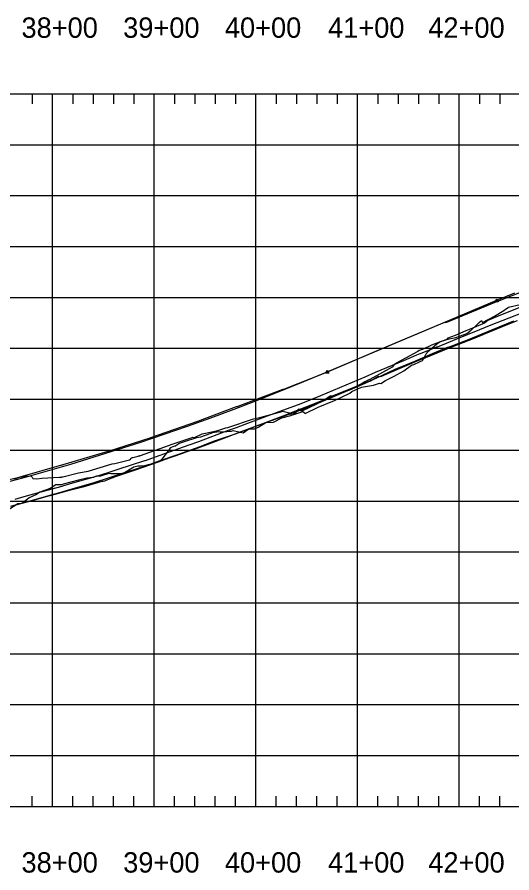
# Model space of a CAD drawing. Extents: x 704797 to 712284, y 374940 to 376945.
# Drawn here: x 710899 to 711386, y 375160 to 376001 of the extents above; entities that cross this region are included whole.
import ezdxf

# ---------------------------------------------------------------- set-up
doc = ezdxf.new("R2010")
doc.units = 0
for name, color, linetype in [('10', 7, 'Continuous'), ('12', 7, 'Continuous'), ('13', 7, 'Continuous'), ('48', 7, 'Continuous'), ('61', 7, 'Continuous'), ('Existing', 7, 'Continuous')]:
    doc.layers.add(name, color=color, linetype=linetype)

msp = doc.modelspace()

# ---------------------------------------------------------------- linework, layer by layer
for points in [[(711370.57, 375724.17), (711372.07, 375721.17), (711369.07, 375721.17)], [(711204.02, 375653.89), (711205.52, 375650.89), (711202.52, 375650.89)]]:
    msp.add_lwpolyline(points, close=True)
at = {"layer": '10'}
for points in [[(711395.06, 375716.31), (711375.98, 375708.74), (711361.85, 375702.63), (711358.48, 375700.14), (711346.85, 375695.38), (711340.37, 375692.49), (711329.63, 375688.11), (711322.41, 375685.32), (711321.97, 375685.1), (711321.79, 375684.52), (711320.57, 375683.8), (711306.63, 375678.69), (711298.15, 375674.56), (711294.47, 375673.39), (711293.09, 375672.2), (711273.16, 375661.51), (711270.08, 375659.77), (711267.84, 375657.05), (711245.72, 375644.93), (711245.03, 375644.56), (711240.88, 375642.64), (711238.18, 375640.76), (711230.95, 375637.39), (711208.95, 375628.43), (711206.97, 375628.56), (711199.57, 375623.37), (711178.93, 375613.85), (711175.62, 375615.8), (711172.19, 375611.49), (711167.8, 375609.04), (711159.11, 375606.84), (711150.82, 375602.53), (711143.47, 375602.31), (711136.65, 375597.9), (711132.16, 375595.88), (711126.95, 375596.06), (711121.23, 375592.01), (711117.08, 375592.94), (711111.6, 375594.34), (711111.29, 375594.52), (711109.64, 375593.9), (711107.61, 375593.74), (711105.2, 375593.38), (711099.61, 375593.01), (711098.5, 375593.15), (711096.78, 375593.39), (711095.4, 375593.2), (711093.67, 375592.98), (711092.95, 375592.86), (711091.06, 375592.5), (711088.52, 375591.59), (711079.46, 375588.28), (711075.5, 375587.41), (711063.24, 375583.73), (711058.25, 375581.95), (711057.93, 375581.61), (711053.96, 375578.95), (711053.87, 375579.22), (711050.62, 375577.86), (711049.18, 375577.17), (711048.59, 375576.04), (711048.25, 375574.83), (711047.31, 375574.3), (711041.5, 375566.77), (711039.83, 375564.79), (711033.82, 375562.86), (711030.69, 375561.69), (711027.75, 375560.96), (711022.98, 375559.57), (711017.83, 375559.7), (711013.9, 375558.74), (711004.55, 375553.02), (711000.7, 375552.08), (710991.25, 375552.12), (710989.65, 375552.61), (710989.29, 375552.5), (710981.01, 375549.86), (710977.86, 375550), (710977.02, 375549.73), (710976.06, 375549.48), (710976.03, 375549.47), (710974.67, 375548.8), (710974.3, 375548.58), (710974.06, 375548.62), (710973.74, 375548.68), (710967.55, 375547.87), (710959.49, 375545.99), (710944.43, 375541.98), (710942.84, 375541.51), (710942.59, 375541.39), (710942.57, 375541.35), (710942.46, 375541.45), (710939.77, 375541.42), (710936.97, 375541.39), (710931.6, 375537.6), (710921.46, 375534.22), (710917.95, 375531.87), (710910.98, 375528.55), (710909.09, 375527.4), (710904.54, 375523.57), (710904.15, 375523.34), (710903.33, 375523.06), (710899.81, 375522.54), (710890.51, 375516.7)], [(710896.37, 375547.23), (710901.24, 375548.79), (710907.58, 375549.96), (710907.95, 375549.99), (710912.5, 375550.31), (710913.73, 375548.73), (710914.51, 375547.66), (710918.45, 375547.33), (710923.29, 375547.83), (710940.85, 375548.87), (710942.19, 375548.86), (710942.84, 375548.99), (710943.47, 375549.06), (710943.96, 375549.11), (710959.48, 375553), (710968.83, 375554.71), (710992.64, 375561.82), (710994.98, 375562.28), (711009.52, 375566.03), (711009.54, 375566.03), (711009.55, 375566.04), (711009.58, 375566.05), (711010.53, 375566.55), (711010.76, 375567.2), (711011.07, 375567.92), (711011.17, 375567.93), (711011.21, 375567.94), (711011.54, 375567.97), (711011.68, 375567.99), (711012.4, 375568.07), (711012.67, 375568.12), (711018.19, 375569.66), (711018.8, 375569.79), (711019.16, 375569.87), (711019.41, 375569.92), (711019.73, 375569.98), (711019.93, 375570.01), (711019.97, 375570.02), (711020.08, 375570.03), (711020.23, 375570.08), (711048.96, 375580.34), (711050.35, 375580.87), (711070.1, 375587.67), (711071.7, 375588.16), (711073.41, 375587.77), (711073.7, 375587.95), (711074.19, 375588.18), (711081.09, 375591.32), (711090.57, 375593.31), (711092.19, 375593.78), (711097.27, 375595.21), (711104.15, 375597.24), (711106.29, 375597.8), (711131.59, 375606.34), (711137.8, 375607.51), (711160.58, 375613.81), (711161.45, 375613.37), (711161.63, 375613.42), (711166.97, 375612.09), (711168.4, 375610.45), (711168.63, 375610.39), (711170.2, 375610.02), (711180, 375613.29), (711182.62, 375611.47), (711182.93, 375611.67), (711194.26, 375617.34), (711195.02, 375617.5), (711210.96, 375624.1), (711226.19, 375631.39), (711228.3, 375633), (711237.67, 375637.26), (711249.45, 375639.37), (711255.36, 375641.06), (711256.81, 375640.92), (711261.35, 375643.91), (711269.67, 375648.2), (711279.43, 375653.24), (711286.96, 375658.92), (711287.92, 375659.24), (711289.18, 375659.41), (711294.59, 375662.05), (711295.43, 375662.58), (711297.54, 375663.55), (711300.19, 375668.1), (711301.24, 375669.99), (711301.75, 375670.58), (711302.67, 375671.91), (711311.41, 375679.68), (711314.04, 375681.64), (711314.15, 375681.65), (711315.27, 375682.23), (711315.43, 375682.03), (711323.95, 375684.6), (711330.56, 375686.12), (711341.19, 375689.95), (711343.37, 375691.7), (711343.44, 375691.96), (711344.95, 375692.86), (711344.95, 375692.62), (711351.63, 375699.2), (711353.32, 375700.92), (711355.71, 375702.87), (711356.67, 375700.84), (711368.33, 375707.09), (711377.46, 375712.54), (711379.09, 375713.99), (711381.95, 375715.67), (711382.1, 375715.75), (711393.61, 375718.55)]]:
    msp.add_lwpolyline(points, dxfattribs=at)
at = {"layer": '12'}
for points in [[(710897.08, 375527.35), (710908.36, 375530.43), (710937.18, 375538.53), (710943.46, 375540.14), (710944.14, 375540.31), (710951.64, 375542.5), (710979.27, 375550.45), (710982.21, 375551.39), (710989.6, 375553.81), (710998.49, 375556.83), (711024.62, 375565.27), (711025.13, 375565.38), (711035.08, 375568.97), (711062.48, 375578.58), (711069.07, 375580.88), (711077.58, 375583.94), (711106.8, 375595.08), (711114.59, 375597.78), (711123.36, 375600.98), (711156.76, 375613.31), (711168.44, 375617.48), (711178.18, 375621.35), (711197.76, 375629.09), (711210.13, 375634.31), (711241.1, 375647.56), (711251.58, 375652.05), (711279.15, 375663.55), (711291.94, 375668.99), (711295.31, 375670.37), (711295.51, 375670.29), (711311.79, 375677.01), (711312.36, 375676.96), (711321.17, 375680.62), (711331.52, 375684.61), (711354.1, 375693.87), (711365.03, 375698.35), (711365.29, 375698.44), (711377, 375703.2), (711402.18, 375713.02)], [(710893.69, 375520.74), (710915.47, 375526.74), (710932.52, 375531.6), (710943.31, 375534.41), (710944.43, 375534.7), (710956.55, 375538.28), (710974.77, 375543.6), (710989.84, 375548.47), (711003.9, 375553.17), (711019.99, 375558.31), (711020.9, 375558.5), (711039.83, 375565.27), (711057.05, 375571.27), (711078.99, 375579.15), (711092.23, 375584.19), (711113.67, 375591.59), (711138.33, 375600.58), (711149.23, 375604.6), (711182.03, 375616.27), (711187.94, 375618.62), (711204.83, 375625.75), (711224.07, 375633.91), (711226.05, 375634.77), (711246.44, 375643.57), (711254.34, 375648.13), (711255.96, 375647.87), (711257.35, 375648.18), (711266.34, 375652.12), (711289.32, 375661.94), (711297.94, 375665.47), (711298.43, 375665.27), (711300.85, 375666.28), (711300.94, 375666.27), (711323.15, 375675.54), (711347.69, 375685.04), (711357.21, 375688.97), (711357.79, 375689.18), (711383.55, 375699.7), (711391.21, 375702.7)]]:
    msp.add_lwpolyline(points, dxfattribs=at)
at = {"layer": '13'}
msp.add_lwpolyline([(711387.06, 375702.05), (711365.47, 375693.43), (711342.44, 375683.93), (711322.95, 375676.34), (711322.75, 375676.5), (711318.86, 375674.9), (711307.26, 375670.06), (711289.66, 375662.52), (711270.52, 375654.53), (711252.28, 375646.06), (711233.02, 375638.06), (711212.95, 375629.5), (711194.32, 375622.11), (711187.97, 375619.62), (711176.11, 375614.93), (711160.34, 375608.66), (711140.28, 375601.28), (711118.88, 375593.27), (711105.61, 375588.32), (711088.05, 375581.6), (711076.63, 375577.31), (711064.98, 375573.36), (711061.68, 375572.2), (711042.56, 375565.47), (711042.17, 375565.3), (711030.14, 375560.99), (711015.08, 375555.8), (710996.28, 375549.62), (710986.32, 375545.55), (710985.02, 375544.99), (710983.69, 375544.62), (710982.21, 375544.58), (710963.51, 375538.95), (710948.06, 375535.04), (710936.1, 375531.91), (710931.13, 375530.63), (710930.77, 375530.64), (710913.53, 375525.73), (710892.38, 375520.16)], dxfattribs=at)
at = {"layer": '48'}
msp.add_line((711204.02, 375652.39), (711370.57, 375722.67), dxfattribs=at)
for points in [[(711370.57, 375722.67), (711379.42, 375726.37), (711388.28, 375730.01)], [(710883.19, 375542.55), (710906.11, 375548.7), (710929.02, 375555.11), (710951.94, 375561.79), (710974.86, 375568.72), (710997.77, 375575.91), (711020.69, 375583.37), (711043.61, 375591.08), (711066.52, 375599.06), (711089.44, 375607.29), (711112.36, 375615.79), (711135.27, 375624.55), (711158.19, 375633.57), (711181.11, 375642.85), (711204.02, 375652.39)]]:
    msp.add_lwpolyline(points, dxfattribs=at)
at = {"layer": '61'}
for p, q in [((708133.69, 375925.47), (712133.69, 375925.47)), ((710913.69, 375925.47), (710913.69, 375915.47)), ((710933.69, 375225.47), (710933.69, 375925.47)), ((710953.69, 375925.47), (710953.69, 375915.47)), ((710973.69, 375925.47), (710973.69, 375915.47)), ((710993.69, 375925.47), (710993.69, 375915.47)), ((711013.69, 375925.47), (711013.69, 375915.47)), ((711033.69, 375225.47), (711033.69, 375925.47)), ((711053.69, 375925.47), (711053.69, 375915.47)), ((711073.69, 375925.47), (711073.69, 375915.47)), ((711093.69, 375925.47), (711093.69, 375915.47)), ((711113.69, 375925.47), (711113.69, 375915.47)), ((711133.69, 375225.47), (711133.69, 375925.47)), ((711153.69, 375925.47), (711153.69, 375915.47)), ((711173.69, 375925.47), (711173.69, 375915.47)), ((711193.69, 375925.47), (711193.69, 375915.47)), ((711213.69, 375925.47), (711213.69, 375915.47)), ((711233.69, 375225.47), (711233.69, 375925.47)), ((711253.69, 375925.47), (711253.69, 375915.47)), ((711273.69, 375925.47), (711273.69, 375915.47)), ((711293.69, 375925.47), (711293.69, 375915.47)), ((711313.69, 375925.47), (711313.69, 375915.47)), ((711333.69, 375225.47), (711333.69, 375925.47)), ((711353.69, 375925.47), (711353.69, 375915.47)), ((711373.69, 375925.47), (711373.69, 375915.47)), ((708133.69, 375875.47), (712133.69, 375875.47)), ((708133.69, 375825.47), (712133.69, 375825.47)), ((708133.69, 375775.47), (712133.69, 375775.47)), ((708133.69, 375725.47), (712133.69, 375725.47)), ((708133.69, 375675.47), (712133.69, 375675.47)), ((708133.69, 375625.47), (712133.69, 375625.47)), ((708133.69, 375575.47), (712133.69, 375575.47)), ((708133.69, 375525.47), (712133.69, 375525.47)), ((708133.69, 375475.47), (712133.69, 375475.47)), ((708133.69, 375425.47), (712133.69, 375425.47)), ((708133.69, 375375.47), (712133.69, 375375.47)), ((708133.69, 375325.47), (712133.69, 375325.47)), ((708133.69, 375275.47), (712133.69, 375275.47)), ((710913.69, 375225.47), (710913.69, 375235.47)), ((710953.69, 375225.47), (710953.69, 375235.47)), ((710973.69, 375225.47), (710973.69, 375235.47)), ((710993.69, 375225.47), (710993.69, 375235.47)), ((711013.69, 375225.47), (711013.69, 375235.47)), ((711053.69, 375225.47), (711053.69, 375235.47)), ((711073.69, 375225.47), (711073.69, 375235.47)), ((711093.69, 375225.47), (711093.69, 375235.47)), ((711113.69, 375225.47), (711113.69, 375235.47)), ((711153.69, 375225.47), (711153.69, 375235.47)), ((711173.69, 375225.47), (711173.69, 375235.47)), ((711193.69, 375225.47), (711193.69, 375235.47)), ((711213.69, 375225.47), (711213.69, 375235.47)), ((711253.69, 375225.47), (711253.69, 375235.47)), ((711273.69, 375225.47), (711273.69, 375235.47)), ((711293.69, 375225.47), (711293.69, 375235.47)), ((711313.69, 375225.47), (711313.69, 375235.47)), ((711353.69, 375225.47), (711353.69, 375235.47)), ((711373.69, 375225.47), (711373.69, 375235.47)), ((708133.69, 375225.47), (712133.69, 375225.47))]:
    msp.add_line(p, q, dxfattribs=at)
at = {"layer": 'Existing'}
msp.add_lwpolyline([(710891.16, 375546.43), (710899.8, 375548.64), (710901.91, 375549.23), (710943.06, 375560.97), (710943.67, 375561.13), (710943.73, 375561.14), (710944.4, 375561.34), (710988.54, 375574.26), (710989.15, 375574.45), (710989.71, 375574.64), (711029.73, 375587.44), (711029.77, 375587.44), (711030.6, 375587.74), (711076.7, 375603.8), (711114.71, 375618.22), (711115.27, 375618.43), (711160.64, 375635.24), (711160.98, 375635.36), (711161.26, 375635.48), (711202, 375651.45), (711203.67, 375652.11), (711247.16, 375670.65), (711249.55, 375671.64), (711251.82, 375672.69), (711293.1, 375689.94), (711295.36, 375690.91), (711319.51, 375700.97), (711319.88, 375701.12), (711320.29, 375700.77), (711323.21, 375701.91), (711370.72, 375721.51), (711373.27, 375722.53), (711412.4, 375737.96)], dxfattribs=at)

# ---------------------------------------------------------------- texts
at = {"layer": '61'}
for s, p in [('38+00', (710903.32, 375980.47)), ('39+00', (711003.32, 375980.47)), ('40+00', (711103.32, 375980.47)), ('41+00', (711204.77, 375980.47)), ('42+00', (711303.32, 375980.47)), ('38+00', (710903.32, 375160.47)), ('39+00', (711003.32, 375160.47)), ('40+00', (711103.32, 375160.47)), ('41+00', (711204.77, 375160.47)), ('42+00', (711303.32, 375160.47))]:
    msp.add_text(s, height=20, dxfattribs=at).set_placement(p)

doc.saveas('drawing.dxf')
